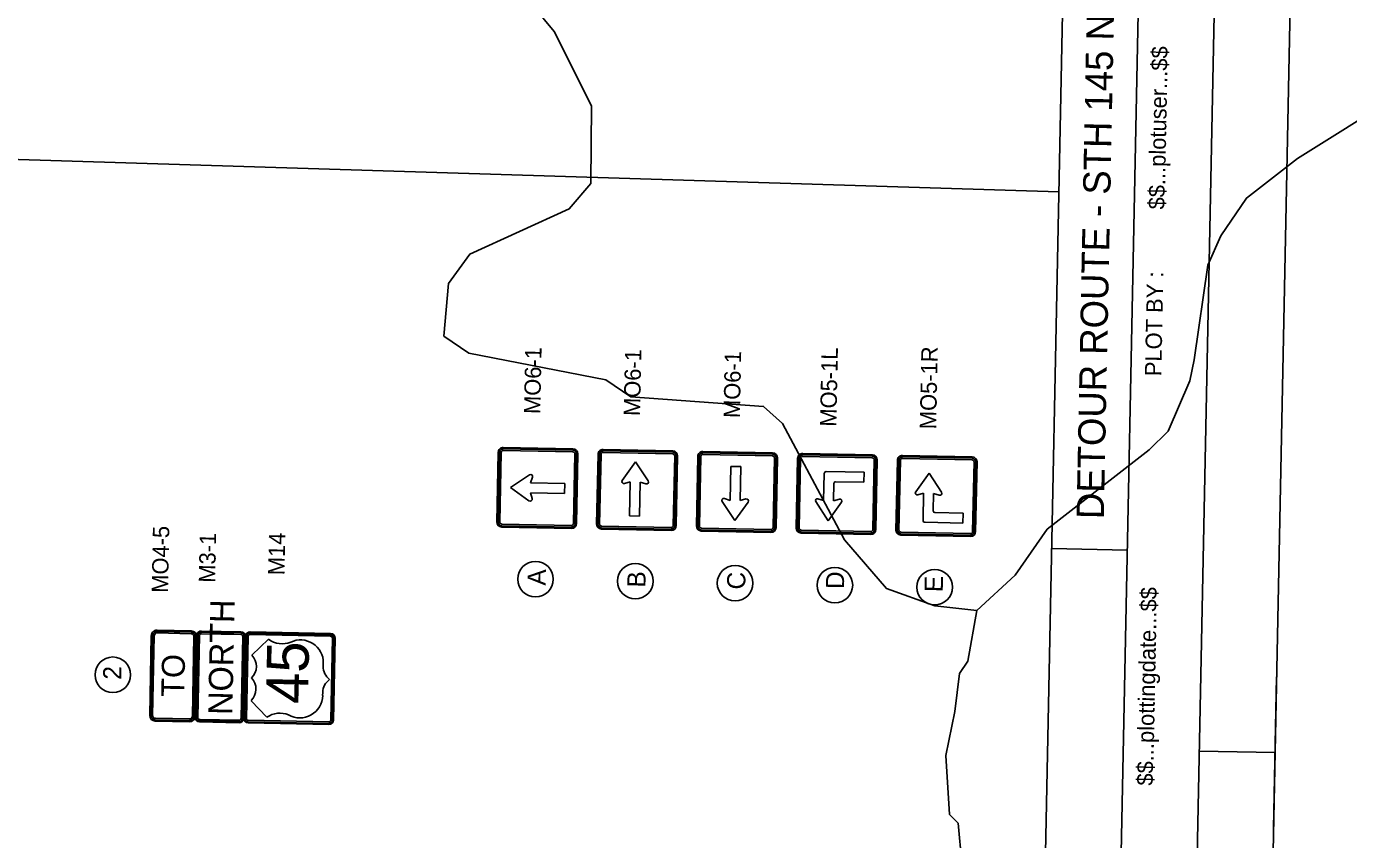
# Model space of a CAD drawing. Extents: x 331323 to 388339, y 121519 to 205315.
# Drawn here: x 363256 to 368485, y 140146 to 143362 of the extents above; entities that cross this region are included whole.
import ezdxf

# ---------------------------------------------------------------- set-up
doc = ezdxf.new("R2010")
doc.units = 0
for name, color, linetype in [('CA-TEXT', 7, 'Continuous'), ('Level 4', 7, 'Continuous'), ('Level 57', 7, 'Continuous'), ('P_RDWY_Text', 7, 'Continuous'), ('P_SGN_Cell', 7, 'Continuous'), ('PLT_Sheet_Border', 7, 'Continuous'), ('PLT_Sheet_Info', 7, 'Continuous')]:
    doc.layers.add(name, color=color, linetype=linetype)

msp = doc.modelspace()

# ---------------------------------------------------------------- linework, layer by layer
at = {"layer": 'CA-TEXT'}
for centre in [(365269.3, 141175.8), (365663.9, 141167.9), (366058.6, 141159.9), (366453.2, 141152), (366847.8, 141144), (363597.8, 140797.5)]:
    msp.add_circle(centre, 70.4, dxfattribs=at)
at = {"layer": 'Level 4'}
msp.add_lwpolyline([(367338.6, 142707.9), (362672.8, 142853), (355637.9, 142792.5)], dxfattribs=at)
at = {"layer": 'Level 57'}
for points in [[(367014.6, 141051.6), (367166.1, 141191.9), (367292.8, 141374.1), (367696, 141687.1), (367771.8, 141761.4), (367857, 141960.7), (367874.5, 142043.8), (367928, 142418.4), (367979.1, 142534.6), (368080.5, 142683.7), (368282.1, 142840.2), (368676.4, 143086.6), (369005.2, 143475.3), (369619.6, 144078.1), (370015, 144449.5), (370611, 144869.2), (370778.7, 144967.6), (370812.1, 144967.3)], [(364906.3, 142137.4), (364924.9, 142345.6), (365009.4, 142461.5), (365403, 142641.2), (365487.4, 142740.5), (365490.2, 143048.8), (365342.8, 143341.8), (365260.3, 143442.5)], [(364906.3, 142137.4), (365005.8, 142069.8), (365546.9, 141964.9), (365646.4, 141897.3), (366171.4, 141859.3), (366245.9, 141791.9), (366491.8, 141331.3), (366656.8, 141138.2), (366848, 141069.8), (367014.6, 141051.6)], [(366907.1, 140244.2), (366892.6, 140477.7), (366927.6, 140652.4), (366945.6, 140802.2), (366979.4, 140851.9), (367014.6, 141051.6)], [(366907.1, 140244.2), (366940.2, 140210.6), (366955.4, 140052.1), (366988.1, 139985.1), (367035.4, 139684.7), (367213.5, 139108.1), (367236.6, 138899.5), (367318.2, 138698.8), (367417, 138556.2), (367681.2, 138270.5), (367771.2, 138086.3), (367834.3, 137694.1), (367933.8, 137626.5), (368233.7, 137590.5), (368324.8, 137523), (368390.2, 137380.7), (368778.5, 136985.5), (369580.4, 136219.9), (370688.4, 135176.5), (371812.8, 134116.3), (371829.2, 134082.8)]]:
    msp.add_lwpolyline(points, dxfattribs=at)
at = {"layer": 'P_RDWY_Text'}
msp.add_lwpolyline([(354790.8, 130527.7), (355201.6, 150923.5), (368398.9, 150657.7), (367988.1, 130261.9)], close=True, dxfattribs=at)
at = {"layer": 'P_SGN_Cell'}
for p, q in [((365417.5, 141691.3), (365142, 141696.8)), ((365121.9, 141677.5), (365116.3, 141402)), ((365121.6, 141401.9), (365127.1, 141677.4)), ((365128.1, 141401.7), (365133.7, 141677.3)), ((365141.7, 141685), (365417.3, 141679.5)), ((365141.8, 141691.6), (365417.4, 141686)), ((365419.4, 141395.9), (365425, 141671.4)), ((365426, 141395.7), (365431.6, 141671.3)), ((365431.3, 141395.6), (365436.8, 141671.2)), ((365516.5, 141669.6), (365510.9, 141394)), ((365516.2, 141393.9), (365521.7, 141669.5)), ((365522.8, 141393.8), (365528.3, 141669.3)), ((365536.3, 141677.1), (365811.9, 141671.5)), ((365536.5, 141683.6), (365812, 141678.1)), ((365812.1, 141683.3), (365536.6, 141688.9)), ((365814.1, 141387.9), (365819.6, 141663.5)), ((365820.6, 141387.8), (365826.2, 141663.4)), ((365825.9, 141387.7), (365831.4, 141663.2)), ((365911.1, 141661.6), (365905.6, 141386.1)), ((365910.8, 141386), (365916.4, 141661.5)), ((365917.4, 141385.8), (365922.9, 141661.4)), ((365931, 141669.1), (366206.5, 141663.6)), ((365931.1, 141675.7), (366206.7, 141670.1)), ((366206.8, 141675.4), (365931.2, 141680.9)), ((366208.7, 141380), (366214.3, 141655.5)), ((366215.3, 141379.8), (366220.8, 141655.4)), ((366220.5, 141379.7), (366226.1, 141655.3)), ((366305.8, 141653.7), (366300.2, 141378.1)), ((366305.5, 141378), (366311, 141653.6)), ((366312, 141377.9), (366317.6, 141653.5)), ((366601.2, 141655.6), (366325.6, 141661.2)), ((366601.3, 141662.2), (366325.7, 141667.7)), ((366601.4, 141667.4), (366325.8, 141673)), ((366603.3, 141372), (366608.9, 141647.6)), ((366609.9, 141371.9), (366615.4, 141647.5)), ((366615.1, 141371.8), (366620.7, 141647.3)), ((366700.4, 141645.7), (366694.8, 141370.2)), ((366700.1, 141370.1), (366705.6, 141645.6)), ((366706.7, 141369.9), (366712.2, 141645.5)), ((366995.8, 141647.7), (366720.2, 141653.2)), ((366995.9, 141654.2), (366720.4, 141659.8)), ((366996, 141659.5), (366720.5, 141665)), ((365665.1, 141639.9), (365612.5, 141566.7)), ((365714.7, 141564.6), (365665.1, 141639.9)), ((366041.7, 141621.9), (366039, 141487.4)), ((366081.1, 141621.1), (366041.7, 141621.9)), ((366078.4, 141486.6), (366081.1, 141621.1)), ((366408.7, 141486.9), (366410.9, 141593.8)), ((366418.9, 141601.5), (366568.5, 141598.5)), ((366568.5, 141598.5), (366567.7, 141559.1)), ((366825.4, 141594.6), (366772.8, 141521.3)), ((366875, 141519.3), (366825.4, 141594.6)), ((366998, 141364.1), (367003.5, 141639.6)), ((367004.5, 141363.9), (367010.1, 141639.5)), ((367009.8, 141363.8), (367015.3, 141639.4)), ((365245.6, 141588.3), (365170.3, 141538.7)), ((365170.3, 141538.7), (365243.5, 141486.1)), ((365250.1, 141556.8), (365257.4, 141579.3)), ((365384.6, 141554.1), (365250.1, 141556.8)), ((365383.8, 141514.7), (365384.6, 141554.1)), ((365621, 141554.5), (365643.8, 141560.9)), ((365643.8, 141560.9), (365641.1, 141426.4)), ((365680.5, 141425.6), (365683.2, 141560.1)), ((365683.2, 141560.1), (365705.7, 141552.8)), ((366449.5, 141555), (366448.1, 141486.1)), ((366567.7, 141559.1), (366456.2, 141561.4)), ((365255.7, 141494.6), (365249.3, 141517.4)), ((365249.3, 141517.4), (365383.8, 141514.7)), ((366039, 141487.4), (366016.5, 141494.7)), ((366101.2, 141493), (366078.4, 141486.6)), ((366386.2, 141494.2), (366408.7, 141486.9)), ((366448.1, 141486.1), (366470.9, 141492.5)), ((366781.3, 141509.2), (366804.1, 141515.6)), ((366804.1, 141515.6), (366802, 141408.7)), ((366842.1, 141445.9), (366843.5, 141514.8)), ((366843.5, 141514.8), (366866, 141507.5)), ((366007.5, 141482.9), (366057.1, 141407.6)), ((366057.1, 141407.6), (366109.7, 141480.8)), ((366426.8, 141407.1), (366377.2, 141482.4)), ((366479.4, 141480.3), (366426.8, 141407.1)), ((366960.1, 141437), (366848.5, 141439.2)), ((366959.3, 141397.6), (366960.1, 141437)), ((365135.6, 141381.9), (365411.2, 141376.3)), ((365135.7, 141387.1), (365411.3, 141381.6)), ((365135.8, 141393.7), (365411.4, 141388.1)), ((365530.5, 141385.7), (365806, 141380.2)), ((365641.1, 141426.4), (365680.5, 141425.6)), ((366809.7, 141400.6), (366959.3, 141397.6)), ((365530.2, 141373.9), (365805.8, 141368.4)), ((365530.3, 141379.2), (365805.9, 141373.6)), ((365924.9, 141366), (366200.4, 141360.4)), ((365925, 141371.2), (366200.5, 141365.7)), ((365925.1, 141377.8), (366200.7, 141372.3)), ((366319.5, 141358), (366595.1, 141352.5)), ((366595.2, 141357.7), (366319.6, 141363.3)), ((366595.3, 141364.3), (366319.7, 141369.9)), ((366714.1, 141350.1), (366989.7, 141344.5)), ((366989.8, 141349.8), (366714.2, 141355.3)), ((366989.9, 141356.4), (366714.4, 141361.9)), ((363948.2, 140970.6), (364104.2, 140967.5)), ((363948.2, 140966.1), (364104.1, 140963)), ((364140.1, 140962.4), (364459, 140955.9)), ((364140.2, 140966.9), (364459.1, 140960.4)), ((363923.4, 140628.8), (363929.9, 140953)), ((363927.9, 140629), (363934.4, 140952.9)), ((363933.9, 140628.8), (363940.4, 140952.8)), ((363948, 140960.1), (364104, 140957)), ((364111.3, 140949.3), (364104.8, 140625.4)), ((364117.3, 140949.2), (364110.8, 140625.3)), ((364115.3, 140625.1), (364121.8, 140949.2)), ((364121.8, 140949.1), (364115.3, 140625.2)), ((364119.8, 140625.2), (364126.3, 140949.1)), ((364125.8, 140625.1), (364132.3, 140949)), ((364140, 140956.4), (364458.9, 140949.9)), ((364147.8, 140875), (364213.4, 140938)), ((364466.2, 140942.3), (364459.7, 140618.4)), ((364472.2, 140942.2), (364465.7, 140618.2)), ((364476.7, 140942.1), (364470.2, 140618.1)), ((364430.1, 140843.6), (364429.9, 140830.8)), ((364427.8, 140727.9), (364427.5, 140715.1)), ((364128.9, 140677.3), (364128.9, 140677.3)), ((364207.2, 140629.5), (364144.2, 140695)), ((363941, 140610.7), (364097, 140607.5)), ((363941.1, 140615.2), (364097.1, 140612)), ((363941.2, 140621.2), (364097.2, 140618)), ((364133, 140611.4), (364451.9, 140605)), ((364133, 140606.9), (364451.8, 140600.5)), ((364133.2, 140617.4), (364452.1, 140611))]:
    msp.add_line(p, q, dxfattribs=at)
for points in [[(363907.5, 140960.1), (363772.5, 140962.8)], [(363907.6, 140965.7), (363772.7, 140968.4)], [(363907.7, 140971.3), (363772.8, 140974)], [(363749.8, 140952), (363743.5, 140637)], [(363755.5, 140951.9), (363749.1, 140636.9)], [(363761.1, 140951.8), (363754.7, 140636.8)], [(363912.2, 140633.6), (363918.5, 140948.6)], [(363917.8, 140633.5), (363924.2, 140948.5)], [(363923.4, 140633.4), (363929.8, 140948.4)], [(363765.5, 140614.1), (363900.5, 140611.4)], [(363765.6, 140619.7), (363900.6, 140617)], [(363765.8, 140625.3), (363900.7, 140622.6)]]:
    msp.add_lwpolyline(points, dxfattribs=at)
for centre, radius, start, end in [((365141.6, 141677.1), 19.7, 88.8468, 178.8468), ((365141.6, 141677.1), 19.7, 149.4503, 178.8468), ((365141.6, 141677.1), 14.4, 88.8468, 178.8468), ((365141.6, 141677.1), 7.87, 88.8468, 178.8468), ((365417.1, 141671.6), 7.87, 358.8468, 88.8468), ((365417.1, 141671.6), 14.4, 358.8468, 88.8468), ((365417.1, 141671.6), 19.7, 358.8468, 88.8468), ((365536.2, 141669.2), 19.7, 88.8468, 178.8468), ((365536.2, 141669.2), 19.7, 149.4503, 178.8468), ((365536.2, 141669.2), 14.4, 88.8468, 178.8468), ((365536.2, 141669.2), 7.87, 88.8468, 178.8468), ((365811.7, 141663.6), 7.87, 358.8468, 88.8468), ((365811.7, 141663.6), 14.4, 358.8468, 88.8468), ((365811.7, 141663.6), 19.7, 358.8468, 88.8468), ((365930.8, 141661.2), 19.7, 88.8468, 178.8468), ((365930.8, 141661.2), 19.7, 149.4503, 178.8468), ((365930.8, 141661.2), 14.4, 88.8468, 178.8468), ((365930.8, 141661.2), 7.87, 88.8468, 178.8468), ((366206.4, 141655.7), 7.87, 358.8468, 88.8468), ((366206.4, 141655.7), 14.4, 358.8468, 88.8468), ((366206.4, 141655.7), 19.7, 358.8468, 88.8468), ((366325.4, 141653.3), 19.7, 88.8462, 178.8462), ((366325.4, 141653.3), 14.4, 88.8462, 178.8462), ((366325.4, 141653.3), 7.87, 88.8462, 178.8462), ((366601, 141647.7), 7.87, 358.8462, 88.8462), ((366601, 141647.7), 14.4, 358.8462, 88.8462), ((366601, 141647.7), 19.7, 358.8462, 88.8462), ((366720.1, 141645.3), 19.7, 88.8462, 178.8462), ((366720.1, 141645.3), 14.4, 88.8462, 178.8462), ((366720.1, 141645.3), 7.87, 88.8462, 178.8462), ((366995.6, 141639.8), 7.87, 358.8462, 88.8462), ((366995.6, 141639.8), 14.4, 358.8462, 88.8462), ((366995.6, 141639.8), 19.7, 358.8462, 88.8462), ((365249.9, 141581.7), 7.87, 342.0442, 123.3765), ((366418.8, 141593.7), 7.87, 88.8462, 178.8462), ((365618.9, 141562.1), 7.87, 144.3172, 285.6494), ((365708.1, 141560.3), 7.87, 252.0442, 33.3765), ((366456.1, 141554.8), 6.56, 88.8462, 178.8462), ((365248.1, 141492.5), 7.87, 234.3172, 15.6494), ((366014.1, 141487.2), 7.87, 72.0442, 213.3765), ((366103.3, 141485.4), 7.87, 324.3172, 105.6494), ((366383.8, 141486.7), 7.87, 72.0436, 213.3759), ((366473, 141484.9), 7.87, 324.3166, 105.6488), ((366779.2, 141516.8), 7.87, 144.3166, 285.6488), ((366868.4, 141515), 7.87, 252.0436, 33.3759), ((366848.6, 141445.8), 6.56, 178.8462, 268.8462), ((365136, 141401.6), 19.7, 178.8468, 268.8468), ((365136, 141401.6), 14.4, 178.8468, 268.8468), ((365136, 141401.6), 7.87, 178.8468, 268.8468), ((365411.6, 141396), 19.7, 268.8468, 358.8468), ((365411.6, 141396), 14.4, 268.8468, 358.8468), ((365411.6, 141396), 7.87, 268.8468, 358.8468), ((365530.6, 141393.6), 19.7, 178.8468, 268.8468), ((365530.6, 141393.6), 14.4, 178.8468, 268.8468), ((365530.6, 141393.6), 7.87, 178.8468, 268.8468), ((365806.2, 141388.1), 19.7, 268.8468, 358.8468), ((365806.2, 141388.1), 14.4, 268.8468, 358.8468), ((365806.2, 141388.1), 7.87, 268.8468, 358.8468), ((365925.3, 141385.7), 19.7, 178.8468, 268.8468), ((365925.3, 141385.7), 14.4, 178.8468, 268.8468), ((365925.3, 141385.7), 7.87, 178.8468, 268.8468), ((366809.8, 141408.5), 7.87, 178.8462, 268.8462), ((366200.8, 141380.1), 19.7, 268.8468, 358.8468), ((366200.8, 141380.1), 14.4, 268.8468, 358.8468), ((366200.8, 141380.1), 7.87, 268.8468, 358.8468), ((366319.9, 141377.7), 19.7, 178.8462, 268.8462), ((366319.9, 141377.7), 14.4, 178.8462, 268.8462), ((366319.9, 141377.7), 7.87, 178.8462, 268.8462), ((366595.5, 141372.2), 19.7, 268.8462, 358.8462), ((366595.5, 141372.2), 14.4, 268.8462, 358.8462), ((366595.5, 141372.2), 7.87, 268.8462, 358.8462), ((366714.5, 141369.8), 19.7, 178.8462, 268.8462), ((366714.5, 141369.8), 14.4, 178.8462, 268.8462), ((366714.5, 141369.8), 7.87, 178.8462, 268.8462), ((366990.1, 141364.2), 19.7, 268.8462, 358.8462), ((366990.1, 141364.2), 14.4, 268.8462, 358.8462), ((366990.1, 141364.2), 7.87, 268.8462, 358.8462), ((363772.3, 140951.5), 22.5, 88.8462, 178.8462), ((363772.3, 140951.5), 16.9, 88.8462, 178.8462), ((363772.3, 140951.5), 11.3, 88.8462, 178.8462), ((363907.3, 140948.8), 16.9, 358.8462, 88.8462), ((363907.3, 140948.8), 22.5, 358.8462, 88.8462), ((363947.9, 140952.6), 18, 88.8462, 178.8462), ((363947.9, 140952.6), 13.5, 88.8462, 178.8462), ((364103.8, 140949.5), 13.5, 358.8462, 88.8462), ((364103.8, 140949.5), 18, 358.8462, 88.8462), ((364139.8, 140948.9), 18, 88.8462, 178.8462), ((364139.8, 140948.9), 13.5, 88.8462, 178.8462), ((363907.3, 140948.8), 11.3, 358.8462, 88.8462), ((363947.9, 140952.6), 7.5, 88.8462, 178.8462), ((364103.8, 140949.5), 7.5, 358.8462, 88.8462), ((364139.8, 140948.9), 7.5, 88.8462, 178.8462), ((364267.4, 141010), 90, 233.1143, 291.9873), ((364340.1, 140845.4), 90, 358.8462, 115.6928), ((364458.7, 140942.4), 7.5, 358.8462, 88.8462), ((364458.7, 140942.4), 13.5, 358.8462, 88.8462), ((364458.7, 140942.4), 18, 358.8462, 88.8462), ((364101, 140831), 64.3, 314.4191, 43.2734), ((364494.9, 140829.8), 65.1, 179.1885, 231.634), ((364099.2, 140741), 64.3, 314.4191, 43.2734), ((364492.9, 140726.2), 65.1, 126.0584, 178.5039), ((364337.6, 140716.9), 90, 240.0981, 358.8463), ((363766, 140636.6), 22.5, 178.8462, 268.8462), ((363766, 140636.6), 16.9, 178.8462, 268.8462), ((363766, 140636.6), 11.3, 178.8462, 268.8462), ((363901, 140633.9), 22.5, 268.8462, 358.8462), ((363901, 140633.9), 16.9, 268.8462, 358.8462), ((363901, 140633.9), 11.3, 268.8462, 358.8462), ((363941.4, 140628.7), 18, 179.6119, 268.8462), ((363941.4, 140628.7), 13.5, 178.8462, 268.8462), ((363941.4, 140628.7), 7.5, 178.8462, 268.8462), ((364097.3, 140625.5), 18, 268.8462, 358.8462), ((364097.3, 140625.5), 13.5, 268.8462, 358.8462), ((364097.3, 140625.5), 7.5, 268.8462, 358.8462), ((364133.3, 140624.9), 18, 179.6119, 268.8462), ((364133.3, 140624.9), 13.5, 178.8462, 268.8462), ((364133.3, 140624.9), 7.5, 178.8462, 268.8462), ((364258.5, 140555.5), 90, 67.7159, 124.7982), ((364452.2, 140618.5), 18, 268.8462, 358.8462), ((364452.2, 140618.5), 13.5, 268.8462, 358.8462), ((364452.2, 140618.5), 7.5, 268.8462, 358.8462)]:
    msp.add_arc(centre, radius, start, end, dxfattribs=at)
at = {"layer": 'PLT_Sheet_Border'}
for points in [[(367988.1, 130261.9), (368398.9, 150657.7), (355201.6, 150923.5), (354790.8, 130527.7)], [(367691.1, 130411.9), (368091, 150267.9), (355493.5, 150521.6), (355093.6, 130665.6)]]:
    msp.add_lwpolyline(points, close=True, dxfattribs=at)
at = {"layer": 'PLT_Sheet_Info'}
for p, q in [((367103.6, 131038.8), (367484.2, 149935)), ((367403.5, 131032.8), (367784.1, 149929)), ((367610.1, 141290.7), (367310.2, 141296.8)), ((368188.1, 140189.8), (368200.1, 140789.7)), ((368194.1, 140489.7), (367894.2, 140495.8))]:
    msp.add_line(p, q, dxfattribs=at)

# ---------------------------------------------------------------- texts
at = {"layer": 'CA-TEXT'}
for s, p in [('A', (365309.1, 141150.2)), ('B', (365703.8, 141142.2)), ('C', (366098.4, 141134.3)), ('D', (366489.3, 141136.2)), ('E', (366879.7, 141123.8)), ('2', (363630.9, 140777.5))]:
    msp.add_text(s, height=72, rotation=88.8468, dxfattribs=at).set_placement(p)
at = {"layer": 'P_SGN_Cell'}
for s, height, rotation, p in [('MO6-1', 64.8, 88.8468, (365288.1, 141828.6)), ('MO6-1', 64.8, 88.8468, (365682.8, 141820.7)), ('MO6-1', 64.8, 88.8468, (366077.4, 141812.7)), ('MO5-1L', 64.8, 88.8462, (366459, 141778.4)), ('MO5-1R', 64.8, 88.8462, (366853.6, 141768.5)), ('MO4-5', 64.8, 88.8462, (363815.9, 141121.2)), ('M3-1', 64.8, 88.8462, (364002.3, 141161.1)), ('M14', 64.8, 88.8462, (364276.4, 141190.9)), ('NORTH', 96, 88.8462, (364070.5, 140637.8)), ('45', 165.6, 88.8462, (364368.8, 140681.5)), ('TO', 91.2, 88.8462, (363880.1, 140709.2))]:
    msp.add_text(s, height=height, rotation=rotation, dxfattribs=at).set_placement(p)
at = {"layer": 'PLT_Sheet_Info'}
for s, height, p in [('DETOUR ROUTE - STH 145 NB ON RAMP                    ', 108, (367516.6, 141412.6)), ('$$...plotuser...$$', 64.8, (367757.3, 142638)), ('PLOT BY :', 64.8, (367744, 141978.2)), ('$$...plottingdate...$$', 64.8, (367711.4, 140358.5))]:
    msp.add_text(s, height=height, rotation=88.8462, dxfattribs=at).set_placement(p)

doc.saveas('drawing.dxf')
